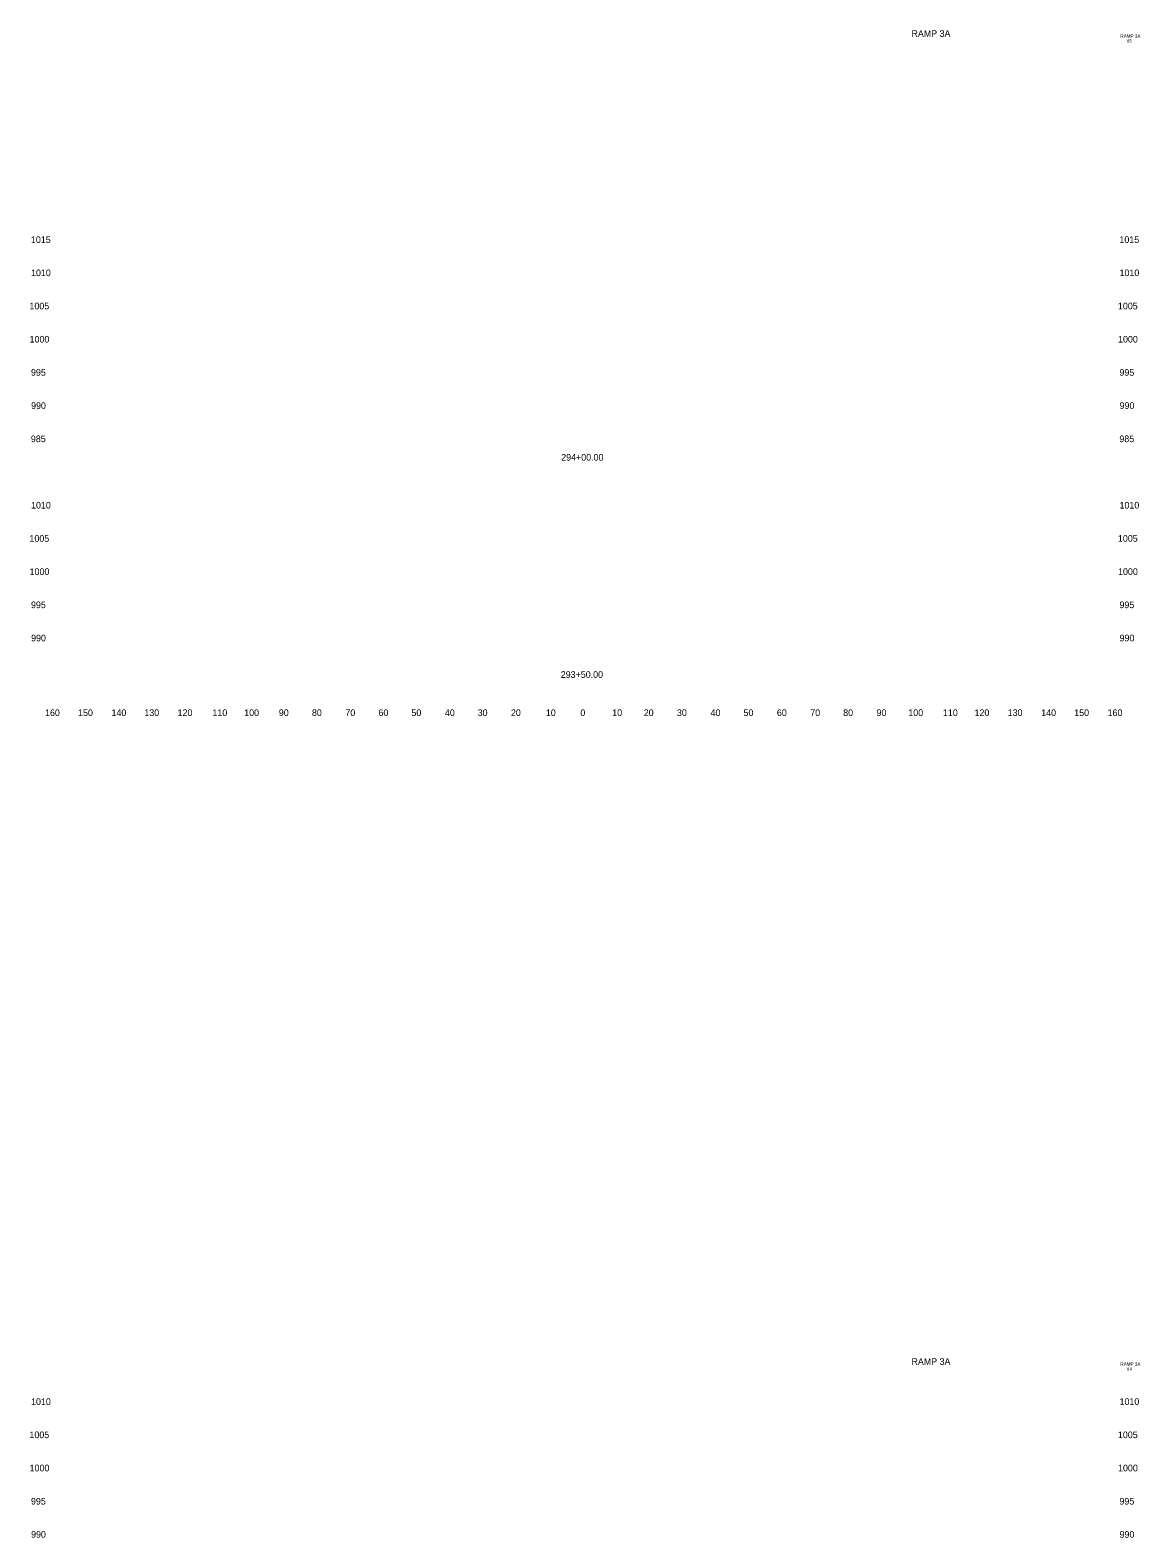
# Model space of a CAD drawing. Extents: x 4286 to 5843, y 4997 to 8804.
# Drawn here: x 4993.6 to 5327.8, y 6350 to 6804.1 of the extents above; entities that cross this region are included whole.
import ezdxf

# ---------------------------------------------------------------- set-up
doc = ezdxf.new("R2010")
doc.units = 0
for name, color, linetype in [('RD_SHT_ID', 7, 'Continuous'), ('RD_XS_TX_Offset', 7, 'Continuous'), ('RD_XS_TX_Station', 7, 'Continuous')]:
    doc.layers.add(name, color=color, linetype=linetype)

msp = doc.modelspace()

# ---------------------------------------------------------------- texts
at = {"layer": 'RD_SHT_ID'}
for s, height, p in [('RAMP 3A', 2, (5259.02, 6802.06)), ('RAMP 3A', 1, (5321.93, 6801.8)), ('X5', 1, (5323.74, 6800.3)), ('RAMP 3A', 2, (5259.02, 6402.06)), ('RAMP 3A', 1, (5321.93, 6401.8)), ('X4', 1, (5323.74, 6400.3))]:
    msp.add_text(s, height=height, dxfattribs=at).set_placement(p)
at = {"layer": 'RD_XS_TX_Offset'}
for s, p in [('1015', (4993.85, 6740)), ('1015', (5321.65, 6740)), ('1010', (4993.88, 6730)), ('1010', (5321.68, 6730)), ('1005', (4993.4, 6720)), ('1005', (5321.2, 6720)), ('1000', (4993.44, 6710)), ('1000', (5321.24, 6710)), ('995', (4993.86, 6700)), ('995', (5321.66, 6700)), ('990', (4993.89, 6690)), ('990', (5321.69, 6690)), ('985', (4993.83, 6680)), ('985', (5321.63, 6680)), ('1010', (4993.88, 6660)), ('1010', (5321.68, 6660)), ('1005', (4993.4, 6650)), ('1005', (5321.2, 6650)), ('1000', (4993.44, 6640)), ('1000', (5321.24, 6640)), ('995', (4993.86, 6630)), ('995', (5321.66, 6630)), ('990', (4993.89, 6620)), ('990', (5321.69, 6620)), ('160', (4998.1, 6597.5)), ('150', (5008.04, 6597.5)), ('140', (5018.1, 6597.5)), ('130', (5027.99, 6597.5)), ('120', (5038.01, 6597.5)), ('110', (5048.51, 6597.5)), ('100', (5058.07, 6597.5)), ('90', (5068.5, 6597.5)), ('80', (5078.46, 6597.5)), ('70', (5088.54, 6597.5)), ('60', (5098.5, 6597.5)), ('50', (5108.43, 6597.5)), ('40', (5118.5, 6597.5)), ('30', (5128.39, 6597.5)), ('20', (5138.4, 6597.5)), ('10', (5148.91, 6597.5)), ('0', (5159.3, 6597.5)), ('0', (5159.3, 6597.5)), ('10', (5168.91, 6597.5)), ('20', (5178.4, 6597.5)), ('30', (5188.39, 6597.5)), ('40', (5198.5, 6597.5)), ('50', (5208.43, 6597.5)), ('60', (5218.5, 6597.5)), ('70', (5228.54, 6597.5)), ('80', (5238.46, 6597.5)), ('90', (5248.5, 6597.5)), ('100', (5258.07, 6597.5)), ('110', (5268.51, 6597.5)), ('120', (5278.01, 6597.5)), ('130', (5287.99, 6597.5)), ('140', (5298.1, 6597.5)), ('150', (5308.04, 6597.5)), ('160', (5318.1, 6597.5)), ('1010', (4993.88, 6390)), ('1010', (5321.68, 6390)), ('1005', (4993.4, 6380)), ('1005', (5321.2, 6380)), ('1000', (4993.44, 6370)), ('1000', (5321.24, 6370)), ('995', (4993.86, 6360)), ('995', (5321.66, 6360)), ('990', (4993.89, 6350)), ('990', (5321.69, 6350))]:
    msp.add_text(s, height=2, dxfattribs=at).set_placement(p)
at = {"layer": 'RD_XS_TX_Station'}
for s, p in [('294+00.00', (5153.55, 6674.44)), ('293+50.00', (5153.41, 6609))]:
    msp.add_text(s, height=2, dxfattribs=at).set_placement(p)

doc.saveas('drawing.dxf')
